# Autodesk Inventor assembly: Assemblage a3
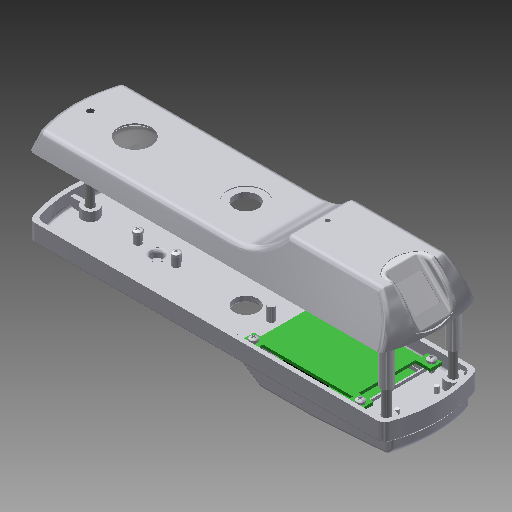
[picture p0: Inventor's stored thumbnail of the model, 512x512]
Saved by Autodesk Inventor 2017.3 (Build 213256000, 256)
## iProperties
Created: 2007-12
Part Number: Assemblage a3
Material: Générique
Document SubType Name: Assembly
Designer: ficho
Author: ficho
Sending System: SolidWorks 2009
Last Author: christophe
Last Saved: 2011-02-10
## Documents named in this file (8)
- G:\travail\année 2019-2020\réforme\toussaint\Serrure biométrique SET\Documentations_pedagogique\Modelisation_Solidworks\Assemblage a3.iam
- G:\travail\année 2019-2020\réforme\toussaint\Serrure biométrique SET\Documentations_pedagogique\Modelisation_Solidworks\pièce a25.ipt
- G:\travail\année 2019-2020\réforme\toussaint\Serrure biométrique SET\Documentations_pedagogique\Modelisation_Solidworks\pièce a23.ipt
- G:\travail\année 2019-2020\réforme\toussaint\Serrure biométrique SET\Documentations_pedagogique\Modelisation_Solidworks\pièce a24.ipt
- G:\travail\année 2019-2020\réforme\toussaint\Serrure biométrique SET\Documentations_pedagogique\Modelisation_Solidworks\piece a27.ipt
- G:\travail\année 2019-2020\réforme\toussaint\Serrure biométrique SET\Documentations_pedagogique\Modelisation_Solidworks\Assemblage a2.iam
- G:\travail\année 2019-2020\réforme\toussaint\Serrure biométrique SET\Documentations_pedagogique\Modelisation_Solidworks\Assemblage a1.iam
- G:\travail\année 2019-2020\réforme\toussaint\Serrure biométrique SET\Documentations_pedagogique\Modelisation_Solidworks\vis4.ipt
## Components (13 placed, 7 different names)
1. pièce a25:1
2. pièce a23:1
3. pièce a24:2
4. piece a27:1
5. piece a27:2
6. Assemblage a2:1 [sub-assembly]
7. Assemblage a1:1 [sub-assembly]
8. vis4:1
9. vis4:2
10. vis4:3
11. vis4:4
12. vis4:5
13. vis4:6
